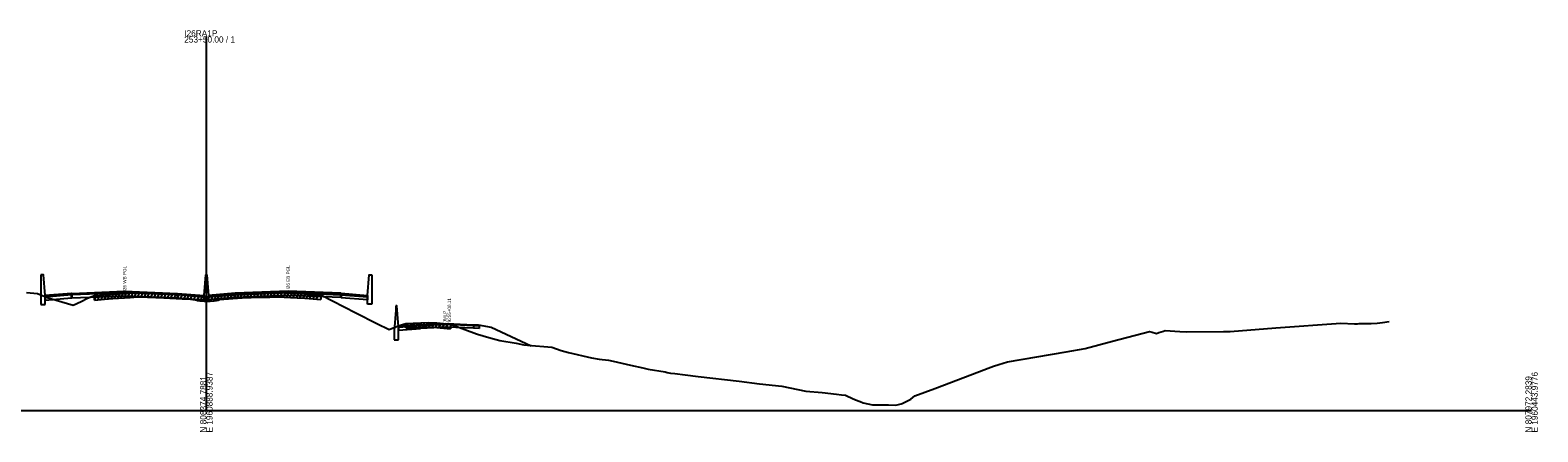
# Model space of a CAD drawing. Extents: x 1017 to 19997, y -1947 to 50737.
# Drawn here: x 10520 to 11203, y 3490 to 3672 of the extents above; entities that cross this region are included whole.
import ezdxf

# ---------------------------------------------------------------- set-up
doc = ezdxf.new("R2010")
doc.units = 0
for name, color, linetype in [('RD_GPK_XS_Cell', 7, 'Continuous'), ('RD_XS_Base', 7, 'Continuous'), ('RD_XS_ExGround', 7, 'Continuous'), ('RD_XS_ExPaveRet', 7, 'Continuous'), ('RD_XS_Greenside', 7, 'Continuous'), ('RD_XS_MedBWall', 7, 'Continuous'), ('RD_XS_Pave', 7, 'Continuous'), ('RD_XS_PaveOvlay', 7, 'Continuous'), ('RD_XS_TX_Notes', 7, 'Continuous')]:
    doc.layers.add(name, color=color, linetype=linetype)

msp = doc.modelspace()

# ---------------------------------------------------------------- linework, layer by layer
at = {"layer": 'RD_GPK_XS_Cell'}
for p, q in [((10600, 3500), (10600, 3669.58)), ((10000, 3500), (10600, 3500)), ((10600, 3500), (11200, 3500))]:
    msp.add_line(p, q, dxfattribs=at)
at = {"layer": 'RD_XS_Base'}
for points in [[(10539, 3552.38), (10527, 3551.42)], [(10527, 3551.42), (10527, 3550.08)], [(10527, 3550.08), (10539, 3551.04)], [(10539, 3551.04), (10539, 3552.38)], [(10539.05, 3551.04), (10539, 3551.04)], [(10539.05, 3552.38), (10539.05, 3551.04)], [(10539.05, 3551.04), (10563, 3552.01), (10587, 3551.05)], [(10587, 3551.05), (10587, 3552.39)], [(10599, 3551.44), (10587, 3552.39)], [(10587, 3551.05), (10599, 3550.1)], [(10599, 3550.1), (10599, 3551.44)], [(10601, 3550.21), (10601, 3551.55)], [(10613, 3551.15), (10601, 3550.21)], [(10613, 3551.15), (10613, 3552.49)], [(10660.95, 3551.15), (10637, 3552.12), (10613, 3551.15)], [(10660.95, 3551.15), (10660.95, 3552.49)], [(10661, 3551.15), (10660.95, 3551.15)], [(10661, 3552.49), (10661, 3551.15)], [(10661, 3552.48), (10673, 3551.52)], [(10661, 3551.14), (10661, 3552.48)], [(10673, 3550.18), (10661, 3551.14)], [(10673, 3551.52), (10673, 3550.18)], [(10697, 3538.58), (10687, 3537.78)], [(10687, 3537.78), (10687, 3536.44)], [(10687, 3536.44), (10697, 3537.24)], [(10697, 3538.58), (10709, 3539.06), (10721, 3538.58)], [(10697, 3537.24), (10697, 3538.58)], [(10721, 3537.26), (10709, 3537.72), (10697, 3537.24)], [(10721, 3538.58), (10721, 3537.26)], [(10721, 3538.58), (10723, 3538.5), (10723.5, 3538.48)], [(10723.5, 3537.14), (10721, 3537.26)], [(10723.5, 3538.48), (10723.5, 3537.14)]]:
    msp.add_lwpolyline(points, dxfattribs=at)
at = {"layer": 'RD_XS_ExGround'}
msp.add_lwpolyline([(10518.55, 3553.45), (10523.62, 3553), (10528.34, 3551.07), (10534.51, 3549.21), (10539.73, 3547.78), (10543.32, 3549.46), (10546.14, 3550.98), (10548.09, 3551.66), (10549.36, 3552.08), (10553.95, 3552.44), (10557.66, 3552.73), (10565.53, 3553.23), (10568.99, 3553.45), (10573.38, 3553.3), (10580.8, 3553.07), (10589.11, 3552.67), (10592.81, 3552.5), (10594.94, 3552.2), (10595.56, 3552.13), (10595.76, 3551.85), (10597.08, 3551.74), (10598.96, 3551.58), (10600, 3551.59), (10600.59, 3551.59), (10601.73, 3551.58), (10603.51, 3551.76), (10604.67, 3551.87), (10604.82, 3552), (10605.4, 3552.08), (10605.74, 3552.11), (10605.9, 3552.32), (10607.24, 3552.46), (10607.98, 3552.51), (10616.29, 3553.02), (10620.28, 3553.27), (10628.76, 3553.44), (10632.15, 3553.51), (10641.13, 3553.09), (10644.62, 3552.93), (10646.57, 3552.77), (10651.86, 3552.38), (10667.7, 3544.27), (10677.2, 3539.5), (10682.73, 3536.66), (10686.83, 3538.38), (10690.32, 3539.42), (10693.66, 3539.53), (10700.54, 3539.94), (10704.33, 3539.67), (10710.58, 3539.09), (10722.26, 3534.76), (10722.76, 3534.55), (10727.9, 3533.05), (10732.88, 3531.74), (10740.26, 3530.53), (10743.75, 3529.71), (10745.46, 3529.56), (10756.41, 3528.65), (10760.67, 3527.14), (10763.9, 3526.34), (10774.42, 3523.92), (10777.85, 3523.21), (10782.05, 3522.75), (10784.17, 3522.33), (10792.09, 3520.62), (10797.65, 3519.36), (10800.07, 3518.75), (10807.71, 3517.51), (10808.64, 3517.27), (10810.19, 3516.91), (10812.08, 3516.74), (10816.86, 3516.11), (10822.6, 3515.47), (10841.28, 3513.36), (10850.44, 3512.13), (10860.55, 3511.05), (10871.41, 3508.77), (10878.83, 3508.23), (10885.29, 3507.46), (10887.56, 3507.12), (10889.42, 3506.97), (10889.73, 3506.79), (10890.24, 3506.54), (10893.91, 3504.81), (10896.02, 3504.07), (10897.4, 3503.5), (10901.64, 3502.55), (10904.03, 3502.54), (10906.24, 3502.52), (10908.9, 3502.5), (10912.12, 3502.48), (10914.64, 3503.01), (10915.1, 3503.24), (10916.56, 3503.93), (10918.92, 3505.12), (10920.81, 3506.58), (10929.89, 3509.92), (10949.99, 3517.7), (10953.95, 3519.18), (10956.38, 3520.11), (10958.76, 3520.88), (10962.65, 3521.99), (10989.35, 3526.66), (10997.9, 3528.08), (11010.19, 3531.41), (11026.95, 3535.88), (11028.2, 3535.45), (11030.2, 3534.97), (11031.26, 3535.34), (11033.28, 3536.01), (11034.05, 3536.23), (11040.78, 3535.77), (11043.55, 3535.67), (11060.46, 3535.76), (11063.54, 3535.77), (11084.16, 3537.43), (11113.7, 3539.56), (11119.83, 3539.36), (11121.21, 3539.34), (11121.97, 3539.43), (11123.33, 3539.42), (11123.81, 3539.44), (11126.87, 3539.51), (11127.32, 3539.5), (11130.14, 3539.66), (11132.52, 3539.87), (11135.47, 3540.36)], dxfattribs=at)
at = {"layer": 'RD_XS_ExPaveRet'}
for p, q in [((10549.36, 3550.08), (10550.4, 3552.17)), ((10549.36, 3550.08), (10549.36, 3552.08)), ((10549.36, 3550.08), (10553.95, 3550.44)), ((10550.86, 3550.2), (10551.9, 3552.28)), ((10552.36, 3550.32), (10553.4, 3552.4)), ((10553.86, 3550.43), (10554.9, 3552.51)), ((10553.95, 3550.44), (10557.66, 3550.73)), ((10555.36, 3550.55), (10556.4, 3552.63)), ((10556.86, 3550.66), (10557.9, 3552.74)), ((10557.66, 3550.73), (10565.53, 3551.23)), ((10558.36, 3550.77), (10559.39, 3552.84)), ((10559.86, 3550.87), (10560.89, 3552.93)), ((10561.36, 3550.96), (10562.39, 3553.03)), ((10562.86, 3551.06), (10563.89, 3553.12)), ((10564.36, 3551.15), (10565.39, 3553.22)), ((10565.53, 3551.23), (10568.99, 3551.45)), ((10565.86, 3551.25), (10566.89, 3553.32)), ((10567.36, 3551.35), (10568.39, 3553.41)), ((10568.86, 3551.44), (10569.85, 3553.42)), ((10568.99, 3551.45), (10573.38, 3551.3)), ((10570.36, 3551.4), (10571.34, 3553.37)), ((10571.86, 3551.35), (10572.84, 3553.32)), ((10573.36, 3551.3), (10574.34, 3553.27)), ((10573.38, 3551.3), (10580.8, 3551.07)), ((10574.86, 3551.26), (10575.84, 3553.23)), ((10576.36, 3551.21), (10577.34, 3553.18)), ((10577.86, 3551.16), (10578.84, 3553.13)), ((10579.36, 3551.11), (10580.34, 3553.08)), ((10580.8, 3551.07), (10589.11, 3550.67)), ((10580.86, 3551.07), (10581.84, 3553.02)), ((10582.36, 3550.99), (10583.34, 3552.95)), ((10583.86, 3550.92), (10584.84, 3552.88)), ((10585.36, 3550.85), (10586.34, 3552.8)), ((10586.86, 3550.78), (10587.84, 3552.73)), ((10588.36, 3550.71), (10589.34, 3552.66)), ((10589.11, 3550.67), (10592.81, 3550.5)), ((10589.86, 3550.63), (10590.84, 3552.59)), ((10591.36, 3550.56), (10592.34, 3552.52)), ((10592.81, 3550.5), (10594.94, 3550.2)), ((10592.86, 3550.49), (10593.79, 3552.36)), ((10594.36, 3550.28), (10595.3, 3552.16)), ((10594.94, 3550.2), (10595.56, 3550.13)), ((10595.56, 3550.13), (10595.76, 3549.85)), ((10595.76, 3549.85), (10597.08, 3549.74)), ((10595.86, 3549.85), (10596.82, 3551.76)), ((10597.08, 3549.74), (10598.96, 3549.58)), ((10597.36, 3549.72), (10598.32, 3551.64)), ((10598.86, 3549.59), (10599.86, 3551.59)), ((10598.96, 3549.58), (10600, 3549.59)), ((10600, 3549.59), (10600.59, 3549.59)), ((10600.36, 3549.59), (10601.36, 3551.58)), ((10600.59, 3549.59), (10601.73, 3549.58)), ((10601.73, 3549.58), (10603.51, 3549.76)), ((10601.86, 3549.59), (10602.91, 3551.7)), ((10603.36, 3549.74), (10604.41, 3551.84)), ((10603.51, 3549.76), (10604.67, 3549.87)), ((10604.67, 3549.87), (10604.82, 3550)), ((10604.82, 3550), (10605.4, 3550.08)), ((10604.86, 3550.01), (10606.02, 3552.33)), ((10605.4, 3550.08), (10605.74, 3550.11)), ((10605.74, 3550.11), (10605.9, 3550.32)), ((10605.9, 3550.32), (10607.24, 3550.46)), ((10606.36, 3550.36), (10607.41, 3552.47)), ((10607.24, 3550.46), (10607.98, 3550.51)), ((10607.86, 3550.5), (10608.89, 3552.57)), ((10607.98, 3550.51), (10616.29, 3551.02)), ((10609.36, 3550.6), (10610.39, 3552.66)), ((10610.86, 3550.69), (10611.89, 3552.75)), ((10612.36, 3550.78), (10613.39, 3552.84)), ((10613.86, 3550.87), (10614.89, 3552.93)), ((10615.36, 3550.96), (10616.39, 3553.02)), ((10616.29, 3551.02), (10620.28, 3551.27)), ((10616.86, 3551.05), (10617.89, 3553.12)), ((10618.36, 3551.15), (10619.39, 3553.21)), ((10619.86, 3551.24), (10620.88, 3553.28)), ((10620.28, 3551.27), (10628.76, 3551.44)), ((10621.36, 3551.29), (10622.37, 3553.31)), ((10622.86, 3551.32), (10623.87, 3553.34)), ((10624.36, 3551.35), (10625.37, 3553.37)), ((10625.86, 3551.38), (10626.87, 3553.4)), ((10627.36, 3551.41), (10628.37, 3553.43)), ((10628.76, 3551.44), (10632.15, 3551.51)), ((10628.86, 3551.44), (10629.87, 3553.47)), ((10630.36, 3551.48), (10631.37, 3553.5)), ((10631.86, 3551.51), (10632.85, 3553.48)), ((10632.15, 3551.51), (10641.13, 3551.09)), ((10633.36, 3551.45), (10634.34, 3553.41)), ((10634.86, 3551.38), (10635.84, 3553.34)), ((10636.36, 3551.31), (10637.34, 3553.27)), ((10637.86, 3551.24), (10638.84, 3553.2)), ((10639.36, 3551.17), (10640.34, 3553.12)), ((10640.86, 3551.1), (10641.84, 3553.06)), ((10641.13, 3551.09), (10644.62, 3550.93)), ((10642.36, 3551.03), (10643.34, 3552.99)), ((10643.86, 3550.97), (10644.83, 3552.92)), ((10644.62, 3550.93), (10646.57, 3550.77)), ((10645.36, 3550.87), (10646.32, 3552.79)), ((10646.57, 3550.77), (10651.86, 3550.38)), ((10646.86, 3550.75), (10647.82, 3552.68)), ((10648.36, 3550.64), (10649.32, 3552.57)), ((10649.86, 3550.53), (10650.82, 3552.45)), ((10651.86, 3552.38), (10651.86, 3550.38)), ((10690.32, 3537.42), (10691.34, 3539.45)), ((10690.32, 3537.42), (10690.32, 3539.42)), ((10690.32, 3537.42), (10693.66, 3537.53)), ((10691.82, 3537.47), (10692.84, 3539.51)), ((10693.32, 3537.52), (10694.35, 3539.57)), ((10693.66, 3537.53), (10700.54, 3537.94)), ((10694.82, 3537.6), (10695.85, 3539.66)), ((10696.32, 3537.69), (10697.35, 3539.75)), ((10697.82, 3537.78), (10698.85, 3539.84)), ((10699.32, 3537.87), (10700.35, 3539.93)), ((10700.54, 3537.94), (10704.33, 3537.67)), ((10700.82, 3537.92), (10701.78, 3539.85)), ((10702.32, 3537.81), (10703.28, 3539.74)), ((10703.82, 3537.7), (10704.78, 3539.63)), ((10704.33, 3537.67), (10710.58, 3537.09)), ((10705.32, 3537.58), (10706.27, 3539.49)), ((10706.82, 3537.44), (10707.77, 3539.35)), ((10708.32, 3537.3), (10709.27, 3539.21)), ((10710.58, 3539.09), (10710.58, 3537.09))]:
    msp.add_line(p, q, dxfattribs=at)
at = {"layer": 'RD_XS_Greenside'}
for points in [[(10723, 3538.81), (10729, 3537.85)], [(10729, 3537.85), (10747.1, 3529.33)]]:
    msp.add_lwpolyline(points, dxfattribs=at)
at = {"layer": 'RD_XS_MedBWall'}
for points in [[(10527, 3552.1), (10526.25, 3561.44), (10525, 3561.44)], [(10525, 3561.44), (10525, 3548.1)], [(10599, 3552.1), (10599.75, 3561.54), (10600.25, 3561.54), (10601, 3552.2)], [(10673, 3552.2), (10673.75, 3561.54), (10675, 3561.54)], [(10675, 3561.54), (10675, 3548.2)], [(10527, 3548.1), (10527, 3552.1)], [(10599, 3550.1), (10599, 3552.1)], [(10601, 3550.1), (10599, 3550.1)], [(10601, 3552.2), (10601, 3550.1)], [(10673, 3548.2), (10673, 3552.2)], [(10525, 3548.1), (10527, 3548.1)], [(10675, 3548.2), (10673, 3548.2)], [(10685.75, 3545.43), (10685, 3536.09)], [(10687, 3538.09), (10686.25, 3547.43), (10685.75, 3547.43)], [(10685.75, 3547.43), (10685.75, 3545.43)], [(10685, 3536.09), (10685, 3532.09)], [(10687, 3532.09), (10687, 3538.09)], [(10685, 3532.09), (10687, 3532.09)]]:
    msp.add_lwpolyline(points, dxfattribs=at)
at = {"layer": 'RD_XS_Pave'}
for points in [[(10539, 3552.72), (10527, 3551.76)], [(10527, 3551.76), (10527, 3551.42)], [(10539, 3552.38), (10539, 3552.72)], [(10539.05, 3552.38), (10539, 3552.38)], [(10539.05, 3552.72), (10563, 3553.69), (10587, 3552.73)], [(10587, 3552.39), (10563, 3553.35), (10539.05, 3552.38)], [(10539.05, 3552.38), (10539.05, 3552.72)], [(10587, 3552.73), (10587, 3552.39)], [(10587, 3552.73), (10599, 3551.78)], [(10599, 3551.78), (10599, 3551.44)], [(10613, 3552.83), (10601, 3551.89)], [(10601, 3551.55), (10613, 3552.49)], [(10601, 3551.89), (10601, 3551.55)], [(10660.95, 3552.83), (10637, 3553.79), (10613, 3552.83)], [(10613, 3552.49), (10637, 3553.46), (10660.95, 3552.49)], [(10613, 3552.83), (10613, 3552.49)], [(10660.95, 3552.49), (10660.95, 3552.83)], [(10660.95, 3552.83), (10661, 3552.83)], [(10661, 3552.49), (10660.95, 3552.49)], [(10661, 3552.83), (10661, 3552.49)], [(10661, 3552.48), (10661, 3552.82)], [(10673, 3551.86), (10673, 3551.52)]]:
    msp.add_lwpolyline(points, dxfattribs=at)
at = {"layer": 'RD_XS_PaveOvlay'}
for points in [[(10539, 3553.06), (10527, 3552.1)], [(10527, 3552.1), (10527, 3551.76)], [(10539.05, 3553.06), (10539, 3553.06)], [(10539, 3553.06), (10539, 3552.72)], [(10539, 3552.72), (10539.05, 3552.72)], [(10539.05, 3553.06), (10563, 3554.02), (10587, 3553.06)], [(10539.05, 3552.72), (10539.05, 3553.06)], [(10587, 3553.06), (10587, 3552.73)], [(10587, 3553.06), (10599, 3552.1)], [(10599, 3552.1), (10599, 3551.78)], [(10613, 3553.16), (10601, 3552.2)], [(10601, 3552.2), (10601, 3551.89)], [(10660.95, 3553.16), (10637, 3554.12), (10613, 3553.16)], [(10613, 3553.16), (10613, 3552.83)], [(10660.95, 3552.83), (10660.95, 3553.16)], [(10660.95, 3553.16), (10661, 3553.16)], [(10661, 3553.16), (10661, 3552.83)], [(10661, 3553.16), (10673, 3552.2)], [(10661, 3552.82), (10661, 3553.16)], [(10673, 3551.86), (10661, 3552.82)], [(10673, 3552.2), (10673, 3551.86)], [(10697, 3538.89), (10687, 3538.09)], [(10687, 3537.78), (10697, 3538.58)], [(10687, 3538.09), (10687, 3537.78)], [(10697, 3538.89), (10709, 3539.37), (10721, 3538.89)], [(10721, 3538.58), (10709, 3539.06), (10697, 3538.58)], [(10697, 3538.58), (10697, 3538.89)], [(10721, 3538.89), (10721, 3538.58)], [(10721, 3538.89), (10723, 3538.81)], [(10723, 3538.5), (10721, 3538.58)], [(10723, 3538.81), (10723, 3538.5)]]:
    msp.add_lwpolyline(points, dxfattribs=at)

# ---------------------------------------------------------------- texts
at = {"layer": 'RD_GPK_XS_Cell'}
for s, p in [('253+50.00 / 1', (10590, 3666.78)), ('I26RA1P', (10590, 3669.58))]:
    msp.add_text(s, height=2.8, dxfattribs=at).set_placement(p)
for s, p in [('E 1960888.9387', (10602.8, 3490)), ('E 1960443.9776', (11202.8, 3490)), ('N 808374.7881', (10600, 3490)), ('N 807972.2839', (11200, 3490))]:
    msp.add_text(s, height=2.8, rotation=90, dxfattribs=at).set_placement(p)
at = {"layer": 'RD_XS_TX_Notes'}
for s, p in [('I26 WB PGL', (10563.75, 3554.02)), ('I26 EB PGL', (10637.75, 3554.86)), (' 9255+06.11', (10710.73, 3539.35)), (' JMLP', (10708.77, 3539.35))]:
    msp.add_text(s, height=1.5, rotation=90, dxfattribs=at).set_placement(p)

doc.saveas('drawing.dxf')
